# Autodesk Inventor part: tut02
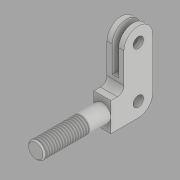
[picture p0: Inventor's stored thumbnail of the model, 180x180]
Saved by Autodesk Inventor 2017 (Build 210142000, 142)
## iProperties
Created: 2015-03
Part Number: tut02
Material: Generic
Document SubType Name: Modeling
Designer: Sandeep
Density: 1 g/cm^3
Appearance: Default
Author: Sandeep
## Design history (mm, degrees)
sketch "Sketch1"
  geometry: L1 (0, 0)-(0, 22); L2 (0, 22)-(5, 22); L3 (10, 27)-(10, 50); L4 (32, 50)-(32, 11); L5 (21, 0)-(0, 0); A1 r 11 centre (21, 50) between (32, 50) and (10, 50); A2 r 11 centre (21, 11) between (21, 0) and (32, 11); A3 r 5 centre (5, 27) between (5, 22) and (10, 27)
  constraints: 10 end point, 6 point on circle, 6 tangent, 3 centre point, 3 perpendicular, 1 parallel, 1 vertical
  dimensions: "d0" = 11 radius of A1; "d1" = 11 radius of A2; "d2" = 5 radius of A3; "d3" = 32 distance between parallel lines of L1 L4; "d4" = 22 distance between parallel lines of L5 L2; "d5" = 50 distance from line of A1.centre L5
extrude "Extrusion1" new body sketch "Sketch1" stored distance "d6" = 13; taper "d7" = 0 deg
hole "Hole1" diameter "d10" = 8; stored, may be unused: countersink angle "d14" = 90 deg, drill point angle "d16" = 118 deg; dims "d8" = 10, "d9" = 10, "d11" = 6, "d12" = 4, "d13" = 2, "d15" = 8
hole "Hole2" diameter "d19" = 8; stored, may be unused: countersink angle "d23" = 90 deg, drill point angle "d25" = 118 deg; dims "d17" = 10, "d18" = 10, "d20" = 6, "d21" = 4, "d22" = 2, "d24" = 8
sketch "Sketch2"
  geometry: L1 (0, -11)-(13, -11) reference; L2 (4, -11)-(4, 20); L3 (4, 20)-(9, 20); L4 (9, 20)-(9, -11); L5 (6.5, 50)-(6.5, -21.602); L6 (13, 50)-(0, 50) reference; L7 (9, -11)-(4, -11)
  constraints: 10 end point, 2 perpendicular, 2 point on line, 2 vertical, 1 collinear, 1 other
  dimensions: "d26" = 5 distance between parallel lines of L4 L2; "d27" = 30 distance between parallel lines of L6 L3
extrude "Extrusion2" cut sketch "Sketch2" stored distance "d28" = 13; taper "d29" = 0 deg
sketch "Sketch3"
  geometry: L1 (13, 0)-(0, 0) reference; L2 (6.5, 0)-(6.5, 35.061); C1 r 6.5 at (6.5, 11)
  constraints: 2 end point, 1 centre point, 1 point on line, 1 vertical
  dimensions: "d30" = 13 diameter of C1; "d31" = 11 distance from line of C1.centre L1
extrude "Extrusion3" join sketch "Sketch3" distance "d32" = 51; taper "d33" = 0 deg
chamfer "Chamfer1" distance "d34" = 1; stored, may be unused: second distance "d35" = 2, angle "d36" = 45 deg
thread "Thread1" dims "d37" = 34, "d38" = 0
body "Solid1"
